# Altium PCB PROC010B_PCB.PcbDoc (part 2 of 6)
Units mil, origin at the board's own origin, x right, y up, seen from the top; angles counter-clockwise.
Board outline 3180 x 2565 mil, 6 copper layers (TOP, L2, L3, L4, L5, BOTTOM), stack 55.54 mil thick; 362 components, 264 nets, 1248 pads, 1144 vias.
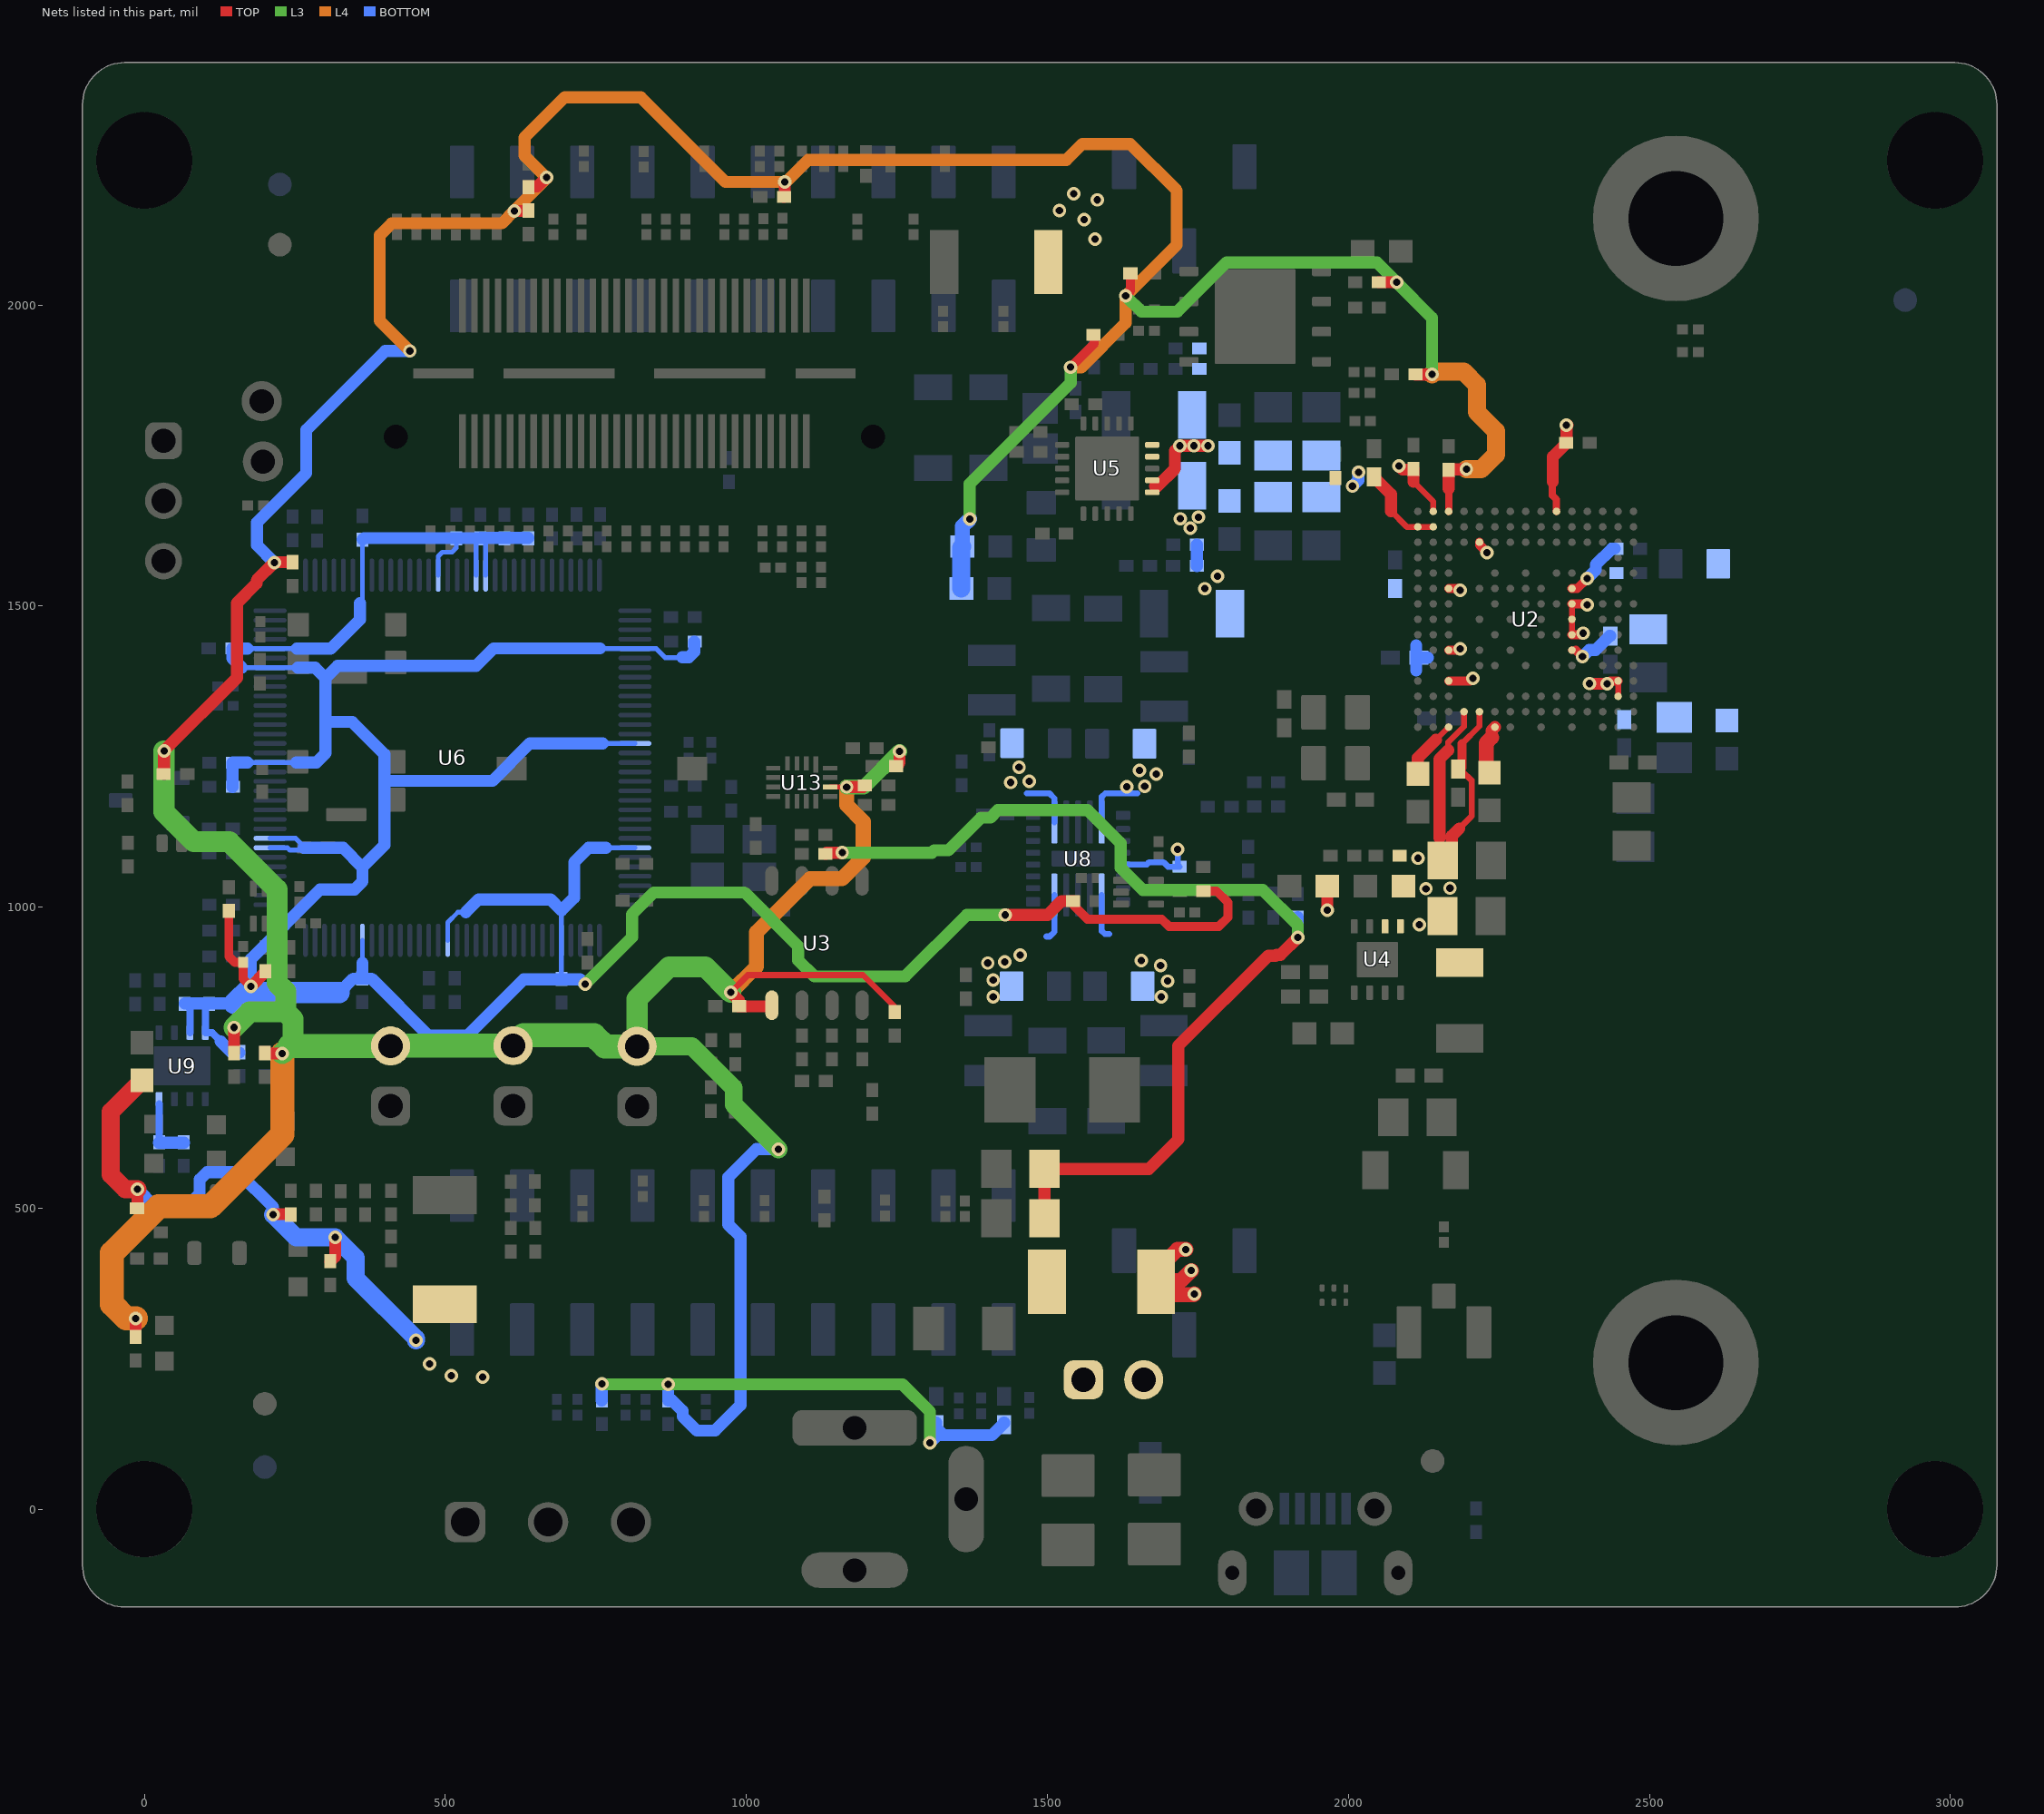
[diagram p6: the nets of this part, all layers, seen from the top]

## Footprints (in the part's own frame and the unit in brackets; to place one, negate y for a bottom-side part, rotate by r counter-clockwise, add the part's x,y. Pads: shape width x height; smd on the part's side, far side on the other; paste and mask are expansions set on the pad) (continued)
PDT0128A [mm] "Thin QFP, 128-Leads, Body 14x14mm, Pitch 0.4mm"
  oval 1.4x0.2 smd: 1(-7.7,6.2) 2(-7.7,5.8) 3(-7.7,5.4) 4(-7.7,5) 5(-7.7,4.6) 6(-7.7,4.2) 7(-7.7,3.8) 8(-7.7,3.4) 9(-7.7,3) 10(-7.7,2.6) 11(-7.7,2.2) 12(-7.7,1.8) 13(-7.7,1.4) 14(-7.7,1) 15(-7.7,0.6) 16(-7.7,0.2) 17(-7.7,-0.2) 18(-7.7,-0.6) 19(-7.7,-1) 20(-7.7,-1.4) 21(-7.7,-1.8) 22(-7.7,-2.2) 23(-7.7,-2.6) 24(-7.7,-3) 25(-7.7,-3.4) 26(-7.7,-3.8) 27(-7.7,-4.2) 28(-7.7,-4.6) 29(-7.7,-5) 30(-7.7,-5.4) 31(-7.7,-5.8) 32(-7.7,-6.2) 65(7.7,-6.2) 66(7.7,-5.8) 67(7.7,-5.4) 68(7.7,-5) 69(7.7,-4.6) 70(7.7,-4.2) 71(7.7,-3.8) 72(7.7,-3.4) 73(7.7,-3) 74(7.7,-2.6) 75(7.7,-2.2) 76(7.7,-1.8) 77(7.7,-1.4) 78(7.7,-1) 79(7.7,-0.6) 80(7.7,-0.2) 81(7.7,0.2) 82(7.7,0.6) 83(7.7,1) 84(7.7,1.4) 85(7.7,1.8) 86(7.7,2.2) 87(7.7,2.6) 88(7.7,3) 89(7.7,3.4) 90(7.7,3.8) 91(7.7,4.2) 92(7.7,4.6) 93(7.7,5) 94(7.7,5.4) 95(7.7,5.8) 96(7.7,6.2)
  oval 0.2x1.4 smd: 33(-6.2,-7.7) 34(-5.8,-7.7) 35(-5.4,-7.7) 36(-5,-7.7) 37(-4.6,-7.7) 38(-4.2,-7.7) 39(-3.8,-7.7) 40(-3.4,-7.7) 41(-3,-7.7) 42(-2.6,-7.7) 43(-2.2,-7.7) 44(-1.8,-7.7) 45(-1.4,-7.7) 46(-1,-7.7) 47(-0.6,-7.7) 48(-0.2,-7.7) 49(0.2,-7.7) 50(0.6,-7.7) 51(1,-7.7) 52(1.4,-7.7) 53(1.8,-7.7) 54(2.2,-7.7) 55(2.6,-7.7) 56(3,-7.7) 57(3.4,-7.7) 58(3.8,-7.7) 59(4.2,-7.7) 60(4.6,-7.7) 61(5,-7.7) 62(5.4,-7.7) 63(5.8,-7.7) 64(6.2,-7.7) 97(6.2,7.7) 98(5.8,7.7) 99(5.4,7.7) 100(5,7.7) 101(4.6,7.7) 102(4.2,7.7) 103(3.8,7.7) 104(3.4,7.7) 105(3,7.7) 106(2.6,7.7) 107(2.2,7.7) 108(1.8,7.7) 109(1.4,7.7) 110(1,7.7) 111(0.6,7.7) 112(0.2,7.7) 113(-0.2,7.7) 114(-0.6,7.7) 115(-1,7.7) 116(-1.4,7.7) 117(-1.8,7.7) 118(-2.2,7.7) 119(-2.6,7.7) 120(-3,7.7) 121(-3.4,7.7) 122(-3.8,7.7) 123(-4.2,7.7) 124(-4.6,7.7) 125(-5,7.7) 126(-5.4,7.7) 127(-5.8,7.7) 128(-6.2,7.7)
  silkscreen extent -7.7,-6.3 6.3,6.99, body extent -8,-8 8,8, height 1.07
RNF0026C [mm] "QFN, 26-Leads, Body 4x4.5mm, Pitch 0.5mm"
  rrect25% 0.6x0.4 smd paste-0.3: 1(-1.9,1.825) 8(-1.9,-1.825) 14(1.9,-1.825) 21(1.9,1.825)
  rrect40% 0.6x0.25 smd paste+0: 2(-1.9,1.25) 3(-1.9,0.75) 4(-1.9,0.25) 5(-1.9,-0.25) 6(-1.9,-0.75) 7(-1.9,-1.25) 15(1.9,-1.25) 16(1.9,-0.75) 17(1.9,-0.25) 18(1.9,0.25) 19(1.9,0.75) 20(1.9,1.25)
  rrect40% 0.25x1.82 smd paste-1: 9(-1,-1.54) 10(-0.5,-1.54) 11(0,-1.54) 12(0.5,-1.54) 13(1,-1.54) 22(1,1.54) 23(0.5,1.54) 24(0,1.54) 25(-0.5,1.54) 26(-1,1.54)
  rrect15% 2.24x0.66 smd paste-1: 27(0,0)
  rrect33% 0.6x0.3 on Bottom Paste: ""(-1.9,-1.775) ""(-1.9,1.775) ""(1.9,-1.775) ""(1.9,1.775)
  rrect33% 0.3x0.825 on Bottom Paste: ""(-1.575,-2.037) ""(-1.575,2.037) ""(1.575,-2.037) ""(1.575,2.037)
  rrect40% 0.25x0.81 on Bottom Paste: ""(-1,-2.045) ""(-1,-1.035) ""(-1,1.035) ""(-1,2.045) ""(-0.5,-2.045) ""(-0.5,-1.035) ""(-0.5,1.035) ""(-0.5,2.045) ""(0,-2.045) ""(0,-1.035) ""(0,1.035) ""(0,2.045) ""(0.5,-2.045) ""(0.5,-1.035) ""(0.5,1.035) ""(0.5,2.045) ""(1,-2.045) ""(1,-1.035) ""(1,1.035) ""(1,2.045)
  rrect15% 0.98x0.66 on Bottom Paste: ""(-0.59,0) ""(0.59,0)
  TOP region: -1.775,1.675 -1.775,2.4 -1.771,2.419 -1.76,2.435 -1.744,2.446 -1.725,2.45 -1.725,2.45 -1.475,2.45 -1.456,2.446 -1.44,2.435 -1.429,2.419 -1.425,2.4 -1.425,2.4 -1.425,1.675 -1.429,1.656 -1.44,1.64 -1.456,1.629 -1.475,1.625 -1.475,1.625 -1.725,1.625 -1.744,1.629 -1.76,1.64 -1.771,1.656 -1.775,1.675
  TOP region: 1.425,1.675 1.425,2.4 1.429,2.419 1.44,2.435 1.456,2.446 1.475,2.45 1.475,2.45 1.725,2.45 1.744,2.446 1.76,2.435 1.771,2.419 1.775,2.4 1.775,2.4 1.775,1.675 1.771,1.656 1.76,1.64 1.744,1.629 1.725,1.625 1.725,1.625 1.475,1.625 1.456,1.629 1.44,1.64 1.429,1.656 1.425,1.675
  TOP region: 1.425,-2.4 1.425,-1.675 1.429,-1.656 1.44,-1.64 1.456,-1.629 1.475,-1.625 1.475,-1.625 1.725,-1.625 1.744,-1.629 1.76,-1.64 1.771,-1.656 1.775,-1.675 1.775,-1.675 1.775,-2.4 1.771,-2.419 1.76,-2.435 1.744,-2.446 1.725,-2.45 1.725,-2.45 1.475,-2.45 1.456,-2.446 1.44,-2.435 1.429,-2.419 1.425,-2.4
  TOP region: -1.775,-2.4 -1.775,-1.675 -1.771,-1.656 -1.76,-1.64 -1.744,-1.629 -1.725,-1.625 -1.725,-1.625 -1.475,-1.625 -1.456,-1.629 -1.44,-1.64 -1.429,-1.656 -1.425,-1.675 -1.425,-1.675 -1.425,-2.4 -1.429,-2.419 -1.44,-2.435 -1.456,-2.446 -1.475,-2.45 -1.475,-2.45 -1.725,-2.45 -1.744,-2.446 -1.76,-2.435 -1.771,-2.419 -1.775,-2.4
  silkscreen extent -2.45,-2.7 2.45,2.7, body extent -2,-2.25 2,2.25, height 0.9
RSV0016A [mm] "QFN, 16-Leads, Body 1.8x2.6mm, Pitch 0.4mm, TI Recommended"
  rect 0.7x0.2 smd: 1(-0.75,0.6)
  rect 0.6x0.2 smd: 2(-0.8,0.2) 3(-0.8,-0.2) 4(-0.8,-0.6) 9(0.8,-0.6) 10(0.8,-0.2) 11(0.8,0.2) 12(0.8,0.6)
  rect 0.2x0.6 smd: 5(-0.6,-1.2) 6(-0.2,-1.2) 7(0.2,-1.2) 8(0.6,-1.2) 13(0.6,1.2) 14(0.2,1.2) 15(-0.2,1.2) 16(-0.6,1.2)
  silkscreen extent -1.08,-1.33 1.08,1.45, body extent -0.92,-1.32 0.92,1.33, height 0.56
RTJ0020D [mm] "QFN, 20-Leads, Body 4x4mm, Pitch 0.5mm, Thermal Pad 2.7x2.7mm, TI Recommended"
  rrect42% 0.6x0.24 smd: 1(-1.9,1) 2(-1.9,0.5) 3(-1.9,0) 4(-1.9,-0.5) 5(-1.9,-1) 11(1.9,-1) 12(1.9,-0.5) 13(1.9,0) 14(1.9,0.5) 15(1.9,1)
  rrect42% 0.24x0.6 smd: 6(-1,-1.9) 7(-0.5,-1.9) 8(0,-1.9) 9(0.5,-1.9) 10(1,-1.9) 16(1,1.9) 17(0.5,1.9) 18(0,1.9) 19(-0.5,1.9) 20(-1,1.9)
  rrect8% 1.19x1.19 on Top Paste: 21(-0.695,-0.695) 21(-0.695,0.695) 21(0.695,-0.695) 21(0.695,0.695)
  rrect4% 2.7x2.7 smd paste-1.4: 21(0,0)
  silkscreen extent -2.22,-2.22 2.23,2.23, body extent -2.07,-2.07 2.08,2.08, height 0.8
Samtec_QSH-030-01-X-D-A [mm] "Receptacle, 0.5 mm, 30x2, TH"
  rect 2.27x0.279 smd: 1(-2.865,7.25) 2(2.865,7.25) 3(-2.865,6.75) 4(2.865,6.75) 5(-2.865,6.25) 6(2.865,6.25) 7(-2.865,5.75) 8(2.865,5.75) 9(-2.865,5.25) 10(2.865,5.25) 11(-2.865,4.75) 12(2.865,4.75) 13(-2.865,4.25) 14(2.865,4.25) 15(-2.865,3.75) 16(2.865,3.75) 17(-2.865,3.25) 18(2.865,3.25) 19(-2.865,2.75) 20(2.865,2.75) 21(-2.865,2.25) 22(2.865,2.25) 23(-2.865,1.75) 24(2.865,1.75) 25(-2.865,1.25) 26(2.865,1.25) 27(-2.865,0.75) 28(2.865,0.75) 29(-2.865,0.25) 30(2.865,0.25) 31(-2.865,-0.25) 32(2.865,-0.25) 33(-2.865,-0.75) 34(2.865,-0.75) 35(-2.865,-1.25) 36(2.865,-1.25) 37(-2.865,-1.75) 38(2.865,-1.75) 39(-2.865,-2.25) 40(2.865,-2.25) 41(-2.865,-2.75) 42(2.865,-2.75) 43(-2.865,-3.25) 44(2.865,-3.25) 45(-2.865,-3.75) 46(2.865,-3.75) 47(-2.865,-4.25) 48(2.865,-4.25) 49(-2.865,-4.75) 50(2.865,-4.75) 51(-2.865,-5.25) 52(2.865,-5.25) 53(-2.865,-5.75) 54(2.865,-5.75) 55(-2.865,-6.25) 56(2.865,-6.25) 57(-2.865,-6.75) 58(2.865,-6.75) 59(-2.865,-7.25) 60(2.865,-7.25)
  round 0 hole 1.02 unplated mask+0: MH1(2.67,10.065) MH2(2.67,-10.065)
  rect 0.43x2.54 smd: MP1(0,8.065) MP4(0,-8.065)
  rect 0.43x4.7 smd: MP2(0,3.175) MP3(0,-3.175)
  silkscreen extent -3.9,-10.66 3.62,10.66, body extent -3.75,-10.64 3.75,10.67, height 3.25
Samtec_SSM-103-x-SV [mm] "Receptacle, 2.54mm, 3x1, SMT"
  rrect10% 1.02x1.905 smd: 1(-2.54,-1.777) 2(0,1.777) 3(2.54,-1.777)
  silkscreen extent -3.81,-2.27 3.81,1.28, body extent -3.81,-2.29 3.81,2.29, height 7.51
Samtec_SSM-110-x-DV [mm] "Receptacle, 2.54mm, 10x2, SMT"
  rrect10% 1.02x2.22 smd: 1(-11.43,2.825) 2(-11.43,-2.825) 3(-8.89,2.825) 4(-8.89,-2.825) 5(-6.35,2.825) 6(-6.35,-2.825) 7(-3.81,2.825) 8(-3.81,-2.825) 9(-1.27,2.825) 10(-1.27,-2.825) 11(1.27,2.825) 12(1.27,-2.825) 13(3.81,2.825) 14(3.81,-2.825) 15(6.35,2.825) 16(6.35,-2.825) 17(8.89,2.825) 18(8.89,-2.825) 19(11.43,2.825) 20(11.43,-2.825)
  silkscreen extent -13.02,-2.54 12.7,2.54, body extent -12.7,-3.52 12.7,3.52, height 7.42
Samtec_TSW-101-17-T-S [mm] "Samtec,CONN HEADER 1POS .100\" SNGL TIN"
  round 1.7 hole 1.02: 1(0,0)
  silkscreen extent -1.27,-1.27 1.27,1.27, body extent -1.27,-1.27 1.27,1.27, height 18.29
Samtec_TSW-103-07-T-S [mm] "Header, 2.54 mm, 3x1, TH"
  rrect50% 1.55x1.55 hole 1.02: 1(-2.54,0)
  round 1.55 hole 1.02: 2(0,0) 3(2.54,0)
  body extent -3.81,-1.27 3.81,1.27, height 8.39
SMB [mil] "Molded Diode, 2-Leads, Body 5.4x3.6mm, IPC Medium Density, based on OnSemi component dimensions"
  rect 85x107.99 smd: 1(-87.01,0) 2(87.01,0)
  silkscreen extent -155,-82 125,82, body extent -106,-71 106,71, height 91
SML-E1_Yellow [mm] "SMD, 2-Leads, Body 1.6x0.8mm"
  rect 0.8x0.8 smd: 1(0.825,0) 2(-0.825,0)
  silkscreen extent -1.8,-0.8 1.3,0.8, body extent -0.85,-0.45 0.85,0.45, height 0.46
SML-LX0603SRW_SuperRed [mm] "Lumex Opto/Components Inc"
  rect 0.8x0.8 smd: 1(-0.75,0) 2(0.75,0)
  silkscreen extent 1.4,-0.53 1.78,0.53, body extent -0.92,-0.53 0.92,0.53, height 1.1
SOD-882 [mm] "Skyworks"
  rrect42% 0.475x0.75 smd: 1(-0.412,0) 2(0.412,0)
  silkscreen extent -1.1,-0.35 -0.87,0.35, body extent -0.5,-0.3 0.5,0.3, height 0.5
SOT-23 [mm] "SOT23, 3-Leads, Body 2.9x1.3mm, Pitch 0.95mm, Lead Span 2.5mm, IPC Medium Density"
  rrect50% 1x0.6 smd: 1(-1.2,0.95) 2(-1.2,-0.95) 3(1.2,0)
  silkscreen extent -1.62,-1.5 0.7,1.5, body extent -1.16,-1.45 1.21,1.45, height 1
SW_CHS-01TB [mm] "CHS Recommended footprint"
  rect 1x1.27 smd: 1(0,3.81) 2(0,-3.81)
  silkscreen extent -1.8,-4.05 1.3,4.05, body extent -1.25,-4 1.25,4, height 2.51
SW_KMR243GLFG [mm] "SMD, 5-Leads, Body 4.2x2.8mm"
  rrect11% 0.9x1 smd: 1(-2.05,0.8) 2(2.05,0.8) 3(-2.05,-0.8) 4(2.05,-0.8)
  rrect18% 1.7x0.55 smd: 5(0,1.425)
  silkscreen extent -3.1,0.7 -2.9,0.9, body extent -2.3,-1.4 2.3,1.4, height 1.92
TI_Stacked_Overlay_Small [mil]
  silkscreen extent -418,-98 418,98
TSW-102-07-G-S [mm] "Samtec 100mil, 1x2, 230 mil above insulator"
  rrect50% 1.65x1.65 hole 1.016: 1(-1.27,0)
  round 1.65 hole 1.016: 2(1.27,0)
  body extent -2.54,-1.27 2.54,1.27, height 8.38
WEEE_Minimum [mil] "WEEElie bin"
  silkscreen extent -95,-172 99,104
WSON-8L_6x5MM_EP [mm] "SMD, 8-Leads, Body 6x5mm, Pitch 1.27mm"
  rrect25% 0.8x0.4 smd: 1(-2.8,1.905) 2(-2.8,0.635) 3(-2.8,-0.635) 4(-2.8,-1.905) 5(2.8,-1.905) 6(2.8,-0.635) 7(2.8,0.635) 8(2.8,1.905)
  rrect3% 3.4x4 smd paste-3: 9(0,0)
  rrect7% 1.468x1.698 on Top Paste: ""(-0.834,-0.949) ""(-0.834,0.949) ""(0.834,-0.949) ""(0.834,0.949)
  silkscreen extent -3.2,-2.7 3.2,2.7, body extent -3.05,-2.55 3.05,2.55, height 0.8

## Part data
C1 C13 C14 C33 C36 C91: library part CMP-0007136-5, "CAP, CERM, 1 uF, 16 V, +/- 10%, X7R, AEC-Q200 Grade 1, 0603", Cap_Case=0603, Manufacturer=MuRata, Supplier Part Number 1=490-5241-6-ND, TempCo=X7R, Tolerance_%=10%, Value1=Unknown, Value2=16V, ValueDisplayed=1uF
C2 C21: library part CMP-0006325-2, "CAP, CERM, 0.1 uF, 50 V, +/- 10%, X7R, AEC-Q200 Grade 1, 0402", Cap_Case=0402, Manufacturer=TDK, Supplier Part Number 1=445-6899-1-ND, TempCo=X7R, Tolerance_%=10%, Value1="0.039064 ohm", Value2=50V, ValueDisplayed=0.1uF
C3 C5 C7 C10 C12 C39 C47 C48 C51 C53 C56 C57 C68: library part CMP-0078265-1, "CAP, CERM, 0.22 µF, 16 V,+/- 10%, X7R, AEC-Q200 Grade 1, 0402", Cap_Case=0402, Manufacturer=MuRata, Supplier Part Number 1=490-10671-1-ND, TempCo=X7R, Tolerance_%=10%, Value2=16V, ValueDisplayed=0.22µF
C4 C6 C11: library part CMP-0006351-2, "CAP, CERM, 0.1 uF, 16 V, +/- 10%, X7R, 0402", Cap_Case=0402, Manufacturer=MuRata, Supplier Part Number 1=490-4759-2-ND, TempCo=X7R, Tolerance_%=10%, Value1=Unknown, Value2=16V, ValueDisplayed=0.1uF
C8: library part CMP-0078219-1, "CAP, CERM, 0.1 µF, 10 V,+/- 10%, X7S, 0201", Cap_Case=0201, Manufacturer=TDK, Supplier Part Number 1=445-9051-1-ND, TempCo=X7S, Tolerance_%=10%, Value2=10V, ValueDisplayed=0.1µF
C9 C15: library part CMP-0006367-2, "CAP, CERM, 4.7 pF, 50 V, +/- 2%, C0G/NP0, 0402", Cap_Case=0402, Manufacturer=MuRata, Supplier Part Number 1=490-8102-1-ND, TempCo=C0G/NP0, Tolerance_%=2%, Value1=Unknown, Value2=50V, ValueDisplayed=4.7pF
C16 C20 C42 C43 C49 C64 C67 C71 C75 C76 C79 C84 C85 C90: library part CMP-0078241-1, "CAP, CERM, 0.1 µF, 10 V,+/- 10%, X7R, 0402", Cap_Case=0402, Manufacturer=Kemet, Supplier Part Number 1=399-3520-1-ND, TempCo=X7R, Tolerance_%=10%, Value2=10V, ValueDisplayed=0.1µF
C17 C19 C23 C32 C34 C35 C37 C38 C40 C45 C52 C58 C59 C60 C65 C72 C73 C83: library part CMP-0008017-2, "CAP, CERM, 10 uF, 10 V, +/- 10%, X7R, 0805", Cap_Case=0805, Manufacturer=MuRata, Supplier Part Number 1=490-10674-1-ND, TempCo=X7R, Tolerance_%=10%, Value1=Unknown, Value2=10V, ValueDisplayed=10uF
C18 C22: library part CMP-0007138-4, "CAP, CERM, 0.47 uF, 16 V, +/- 10%, X7R, AEC-Q200 Grade 1, 0603", Cap_Case=0603, Manufacturer=MuRata, Supplier Part Number 1=490-4775-1-ND, TempCo=X7R, Tolerance_%=10%, Value1=Unknown, Value2=16V, ValueDisplayed=0.47uF
C24: library part CMP-0078221-1, "CAP, CERM, 4700 pF, 50 V,+/- 10%, X7R, 0402", Cap_Case=0402, Manufacturer=TDK, Supplier Part Number 1=445-1258-1-ND, TempCo=X7R, Tolerance_%=10%, Value2=50V, ValueDisplayed=4700pF
C25 C30 C31: library part CMP-0008770-2, "CAP, CERM, 22 uF, 6.3 V, +/- 10%, X7R, AEC-Q200 Grade 1, 1206", Cap_Case=1206_180, Manufacturer=TDK, Supplier Part Number 1=445-7884-1-ND, TempCo=X7R, Tolerance_%=10%, Value1="0.001872 ohm", Value2=6.3V, ValueDisplayed=22uF
C26 C27: library part CMP-0078216-1, "CAP, TA, 47 µF, 10 V, +/- 10%, SMD", Cap_Case=3528-21, Manufacturer=Kemet, Supplier Part Number 1=399-9728-1-ND, Tolerance_%=10%, Value2=10V, ValueDisplayed=47µF
C28 C29 C44 C46: library part CMP-0078224-1, "CAP, CERM, 0.01 µF, 50 V,+/- 10%, X8R, AEC-Q200 Grade 0, 0402", Cap_Case=0402, Manufacturer=TDK, Supplier Part Number 1=445-12303-1-ND, TempCo=X8R, Tolerance_%=10%, Value2=50V, ValueDisplayed=0.01µF
C41 C61 C62: library part CMP-0078222-1, "CAP, CERM, 1 µF, 6.3 V,+/- 20%, X7S, 0402", Cap_Case=0402, Manufacturer=TDK, Supplier Part Number 1=445-9080-1-ND, TempCo=X7S, Tolerance_%=20%, Value2=6.3V, ValueDisplayed=1µF
C50: library part CMP-0078220-1, "CAP, CERM, 0.01 µF, 25 V,+/- 10%, X7R, 0402", Cap_Case=0402, Manufacturer=TDK, Supplier Part Number 1=445-1260-1-ND, TempCo=X7R, Tolerance_%=10%, Value2=25V, ValueDisplayed=0.01µF
C54 C55 C81 C82: library part CMP-0008811-2, "CAP, CERM, 22 uF, 10 V, +/- 10%, X7R, AEC-Q200 Grade 1, 1206", Cap_Case=1206, Manufacturer=MuRata, TempCo=X7R, Tolerance_%=10%, Value1=Unknown, Value2=10V, ValueDisplayed=22uF
C63 C70: library part CMP-0006494-2, "CAP, CERM, 8 pF, 50 V, +/- 6%, C0G/NP0, 0402", Cap_Case=0402, Manufacturer=MuRata, Supplier Part Number 1=490-5867-1-ND, TempCo=C0G/NP0, Tolerance_%=6%, Value1=Unknown, Value2=50V, ValueDisplayed=8pF
C66 C69: library part CMP-0078218-1, "CAP, CERM, 0.01 µF, 16 V,+/- 10%, X7R, 0402", Cap_Case=0402, Manufacturer=Kemet, Supplier Part Number 1=399-1038-1-ND, TempCo=X7R, Tolerance_%=10%, Value2=16V, ValueDisplayed=0.01µF
C74 C77 C80: library part CMP-0006302-2, "CAP, CERM, 2.2 uF, 10 V, +/- 10%, X7S, 0402", Cap_Case=0402_065, Manufacturer=TDK, Supplier Part Number 1=445-9097-1-ND, TempCo=X7S, Tolerance_%=10%, Value1="0.005925 ohm", Value2=10V, ValueDisplayed=2.2uF
C78: library part CMP-0078217-1, "CAP, CERM, 15 pF, 50 V,+/- 1%, C0G/NP0, 0402", Cap_Case=0402, Manufacturer=AVX, Supplier Part Number 1=478-5126-1-ND, TempCo=C0G/NP0, Tolerance_%=1%, Value2=50V, ValueDisplayed=15pF
C86 C87 C88 C89: library part CMP-0078223-1, "CAP, CERM, 390 pF, 50 V,+/- 5%, C0G/NP0, AEC-Q200 Grade 0, 0402", Cap_Case=0402, Manufacturer=TDK, Supplier Part Number 1=445-12137-1-ND, TempCo=C0G/NP0, Tolerance_%=5%, Value2=50V, ValueDisplayed=390pF
"CAUTION HOT SURFACE1": library part CMP-0074837-1, "IEC 61010-1 Hot Surface Warning"
D2: library part CMP-0078187-1, "Diode, Schottky,  V, 0.01 A, SOD-882", Manufacturer="Skyworks Solutions", Value1=0.01A, Value2=0.34V
D3: library part CMP-0078243-1, "Diode, TVS, Uni, 5.8 V, 10.5 Vc, AEC-Q101, SMB", Manufacturer=Littelfuse, Power_W=550mW, Supplier Part Number 1=SZP6SMB6.8AT3G-ND, Value1=0.55W
DS1 DS2 DS5: library part CMP-0002876-1, "LED, Super Red, SMD", Color="super red", Manufacturer=Lumex, Supplier Part Number 1=67-1551-1-ND, Value1=W, Value2=1.7V
DS3 DS4: library part CMP-0002977-2, "LED, Yellow, SMD", Color=yellow, Manufacturer=Rohm, Power_TotalModule=54mW, Supplier Part Number 1=511-1588-1-ND, Value1=0.054W, Value2=2.2V
"ESD Susceptible1": library part CMP-0074840-1, "ESD Susceptible Symbol"
F1: library part CMP-0003458-2, "Fuse, 5 A, 32VAC/VDC, SMD", Irating_A=5A, Manufacturer=Littelfuse, Supplier Part Number 1=F1608CT-ND
FB1 FB2: library part CMP-0003364-1, "Ferrite Bead, 30 ohm @ 100 MHz, 4 A, 0805", Manufacturer=MuRata, Supplier Part Number 1=490-11049-1-ND, Value1="0.014 ohm", Value2=4A, ValueDisplayed="30 ohm"
FID1 FID2 FID3 FID4 FID5 FID6 FID7: library part CMP-0077181-1, "Fiducial mark.  There is nothing to buy or mount.", Manufacturer=N/A
J1: library part CMP-0075524-1, "Receptacle, 0.5 mm, 30x2, Gold, TH", Color=Black, Manufacturer=Samtec, Supplier Part Number 1=SAM8180-ND
J2: library part CMP-0055788-1, "UMC Straight Jack Receptacle, 50 Ohm, Gold, SMT", Manufacturer="Cinch Connectivity", Supplier Part Number 1=J983CT-ND
J3: library part CMP-0075352-1, "Terminal Block, 3.5mm, 3x1, Tin, R/A, TH", Color=Blue, Current_A=10A, Manufacturer="On-Shore Technology", Supplier Part Number 1=ED2636-ND, Voltage_V=125V
J4 J7: library part CMP-0078183-1, "Receptacle, 2.54mm, 3x1, Gold with Tin tail, SMT", Color=Black, Current_A=5.2A, Manufacturer=Samtec, Supplier Part Number 1=SAM1152-03-ND, Voltage_V=405V
J5 J6: library part CMP-0078182-1, "Receptacle, 2.54mm, 10x2, Gold with Tin tail, SMT", Color=Black, Current_A=5.2A, Manufacturer=Samtec, Supplier Part Number 1=SAM1150-10-ND, Voltage_V=405V
J8: library part CMP-0055293-1, "Connector, Receptacle, Micro-USB Type B, R/A, Bottom Mount SMT", Manufacturer=Molex, Supplier Part Number 1=WM1399CT-ND
L1 L2 L3 L4: library part CMP-0058946-1, "Inductor, Shielded, 470 nH, 4.7 A, 0.021 ohm, SMD", Manufacturer="MuRata Toko", PartNumber=DFE252012P-R47M{}P2, Value1="0.021 ohm", Value2=4.7A, ValueDisplayed=470nH
L5 L7 L8 L9: library part CMP-0083745-1, "Inductor, Wirewound, Ferrite, 100 nH, 2.85 A, 0.024 ohm, AEC-Q200 Grade 1, SMD", Manufacturer=TDK, Value1="0.024 ohm", Value2=2.85A, ValueDisplayed=100nH
LBL1: library part CMP-0003625-1, "Thermal Transfer Printable Labels, 0.650\" W x 0.200\" H - 10,000 per roll", Manufacturer=Brady, PartNumber=THT-14-423-10, Supplier Part Number 1=97C5133
Logo1: library part CMP-0074838-1, "Texas Instrument Corporate Signature"
Logo2: library part CMP-0074847-1, "FCC_disclaimer"
Logo3: library part CMP-0074769-1
LOGO4: library part CMP-0074844-1
P1: library part CMP-0075530-2, "Header, 2.54 mm, 3x1, Tin, TH", Color=Black, Current_A=6.3A, Manufacturer=Samtec, Supplier Part Number 1=SAM1035-03-ND, Voltage_V=550V
P2 P3 P4 P5: library part CMP-0075405-2, "Header, 100mil, 2x1, Gold, TH", Color=Black, Current_A=6.3A, Manufacturer=Samtec, Supplier Part Number 1=SAM1029-02-ND, Voltage_V=550V
P6: library part CMP-0078270-1, "DC POWER JACK, R/A, TH", Color=Black, Current_A=5A, Manufacturer="CUI Inc.", Supplier Part Number 1=CP-002AH-ND, Voltage_V=4.5-5.5V
Q1 Q2: library part CMP-0000947-2, "MOSFET, N-CH, 100 V, 0.17 A, SOT-23", Alternate Manufacturer=None, Manufacturer="Fairchild Semiconductor", Supplier Part Number 1=BSS123NCT-ND, Value1=1, Value2="1.8 nC"
R1 R2 R3 R4 R5 R6 R7 R8 R9 R10 R17 R18 R19 R20 R21 R22 R23 R24 R25 R26 R27 R28 R29 R30 R31 R32 R33 R35 R36 R48 R49 R50 R51 R52 R53 R54 R55 R56 R57 R58 R59 R60 R61 R62 R63 R64 R65 R66 R67 R69 R70 R71 R72 R75 R76 R94 R102 R104 R105 R106 R108 R109 R111 R135 R136 R144 R146 R162 R163 R164 R165 R166 R167 R168 R169 R180 R181 R182 R185 R186 R188 R197 R198: library part CMP-0027008-4, "RES, 0, 5%, 0.05 W, 0201", Manufacturer=Vishay-Dale, Power_W=50mW, Supplier Part Number 1=72M6743, TempCo=ppm/C, Tolerance_%=5%, Value2=0.05W, Value_Code=0000, ValueDisplayed=0
R11 R12 R37 R78 R97 R107 R119 R120 R128 R129 R141 R152 R159 R177 R183 R187: library part CMP-0026992-2, "RES, 0, 5%, 0.063 W, 0402", Manufacturer=Panasonic, Power_W=63mW, Supplier Part Number 1=P0.0JCT-ND, TempCo="600 ppm/C", Tolerance_%=5%, Value2=0.063W, Value_Code=0000, ValueDisplayed=0
R13 R14 R15 R16 R41 R43 R46 R47 R73 R74 R81 R83 R84 R86 R89 R91 R98 R113 R145 R148 R155 R178 R179 R184 R196: library part CMP-0025958-3, "RES, 10.0 k, 1%, 0.063 W, AEC-Q200 Grade 0, 0402", Manufacturer=Vishay-Dale, Power_W=63mW, Supplier Part Number 1=541-10.0KLCT-ND, TempCo="100 ppm/C", Tolerance_%=1%, Value2=0.063W, Value_Code=10k0, ValueDisplayed=10.0k
R34 R115 R118: library part CMP-0016044-3, "RES, 0, 5%, 0.75 W, AEC-Q200 Grade 0, 2010", Manufacturer=Vishay-Dale, Power_W=750mW, Supplier Part Number 1=541-0.0WCT-ND, TempCo=ppm/C, Tolerance_%=5%, Value2=0.75W, Value_Code=0000, ValueDisplayed=0
R38: library part CMP-0026395-2, "RES, 47.5 k, 1%, 0.063 W, AEC-Q200 Grade 0, 0402", Manufacturer=Vishay-Dale, Power_W=63mW, Supplier Part Number 1=541-47.5KLCT-ND, TempCo="100 ppm/C", Tolerance_%=1%, Value2=0.063W, Value_Code=47k5, ValueDisplayed=47.5k
R39 R40 R42 R44 R45: library part CMP-0027275-3, "RES, 33.2, 1%, 0.05 W, 0201", Manufacturer=Vishay-Dale, Power_W=50mW, Supplier Part Number 1=541-33.2ABCT-ND, TempCo="200 ppm/C", Tolerance_%=1%, Value2=0.05W, Value_Code=33R2, ValueDisplayed=33.2
R68 R77 R79 R80 R154: library part CMP-0026993-2, "RES, 100, 5%, 0.1 W, AEC-Q200 Grade 0, 0402", Manufacturer=Panasonic, Power_W=100mW, Supplier Part Number 1=P100JCT-ND, TempCo="200 ppm/C", Tolerance_%=5%, Value2=0.1W, Value_Code=100R, ValueDisplayed=100
R82: library part CMP-0025993-3, "RES, 12.7 k, 1%, 0.063 W, AEC-Q200 Grade 0, 0402", Manufacturer=Vishay-Dale, Power_W=63mW, Supplier Part Number 1=541-12.7KLCT-ND, TempCo="100 ppm/C", Tolerance_%=1%, Value2=0.063W, Value_Code=12k7, ValueDisplayed=12.7k
R85 R87: library part CMP-0026491-2, "RES, 61.9, 1%, 0.063 W, AEC-Q200 Grade 0, 0402", Manufacturer=Vishay-Dale, Power_W=63mW, Supplier Part Number 1=541-61.9LCT-ND, TempCo="100 ppm/C", Tolerance_%=1%, Value2=0.063W, Value_Code=61R9, ValueDisplayed=61.9
R88 R96 R114: library part CMP-0026574-2, "RES, 82.5 k, 1%, 0.063 W, AEC-Q200 Grade 0, 0402", Manufacturer=Vishay-Dale, Power_W=63mW, Supplier Part Number 1=541-82.5KLCT-ND, TempCo="100 ppm/C", Tolerance_%=1%, Value2=0.063W, Value_Code=82k5, ValueDisplayed=82.5k
R90 R189: library part CMP-0078194-1, "RES, 360, 5%, 0.1 W, AEC-Q200 Grade 0, 0402", Manufacturer=Panasonic, Power_W=100mW, Supplier Part Number 1=P360JCT-ND, TempCo="200 ppm/C", Tolerance_%=5%, Value2=0.1W, Value_Code=360R, ValueDisplayed=360
R92 R95 R99: library part CMP-0026557-2, "RES, 7.87 k, 1%, 0.063 W, AEC-Q200 Grade 0, 0402", Manufacturer=Vishay-Dale, Power_W=63mW, Supplier Part Number 1=541-7.87KLCT-ND, TempCo="100 ppm/C", Tolerance_%=1%, Value2=0.063W, Value_Code=7k87, ValueDisplayed=7.87k
R93 R101 R112: library part CMP-0026542-2, "RES, 750, 1%, 0.063 W, AEC-Q200 Grade 0, 0402", Manufacturer=Vishay-Dale, Power_W=63mW, Supplier Part Number 1=541-750LCT-ND, TempCo="100 ppm/C", Tolerance_%=1%, Value2=0.063W, Value_Code=750R, ValueDisplayed=750
R100 R103 R116 R117 R160: library part CMP-0078212-1, "RES, 510, 5%, 0.1 W, AEC-Q200 Grade 0, 0402", Manufacturer=Panasonic, Power_W=100mW, Supplier Part Number 1=P510JCT-ND, TempCo="200 ppm/C", Tolerance_%=5%, Value2=0.1W, Value_Code=510R, ValueDisplayed=510
R110 R138 R158 R172 R173: library part CMP-0025950-3, "RES, 100 k, 1%, 0.063 W, AEC-Q200 Grade 0, 0402", Manufacturer=Vishay-Dale, Power_W=63mW, Supplier Part Number 1=541-100KLCT-ND, TempCo="100 ppm/C", Tolerance_%=1%, Value2=0.063W, Value_Code=100k
R121 R132: library part CMP-0078211-2, "RES, 3.00 k, 1%, 0.063 W, AEC-Q200 Grade 0, 0402", Manufacturer=Vishay-Dale, Power_W=63mW, Supplier Part Number 1=52K6934, TempCo="100 ppm/C", Tolerance_%=1%, Value2=0.063W, Value_Code=3k00, ValueDisplayed=3.00k
R122 R131 R139: library part CMP-0026099-2, "RES, 1.96 k, 1%, 0.063 W, AEC-Q200 Grade 0, 0402", Manufacturer=Vishay-Dale, Power_W=63mW, Supplier Part Number 1=541-1.96KLCT-ND, TempCo="100 ppm/C", Tolerance_%=1%, Value2=0.063W, Value_Code=1k96, ValueDisplayed=1.96k
R123 R124 R126 R127 R140: library part CMP-0026071-3, "RES, 1.00 k, 1%, 0.063 W, AEC-Q200 Grade 0, 0402", Manufacturer=Vishay-Dale, Power_W=63mW, Supplier Part Number 1=541-1.00KLCT-ND, TempCo="100 ppm/C", Tolerance_%=1%, Value2=0.063W, Value_Code=1k00, ValueDisplayed=1.00k
R125 R195: library part CMP-0025958-2, "RES, 10.0 k, 1%, 0.063 W, 0402", Manufacturer=Vishay-Dale, Power_W=63mW, Supplier Part Number 1=541-10.0KLCT-ND, TempCo="100 ppm/C", Tolerance_%=1%, Value2=0.063W, Value_Code=10k0, ValueDisplayed=10.0k
R130 R133 R137 R161 R175 R176: library part CMP-0025884-3, "RES, 0, 5%, 0.125 W, 0603", Manufacturer=Vishay/Beyschlag, Power_W=125mW, Supplier Part Number 1=MCT0603-0.0-ZZCT-ND, TempCo=ppm/C, Tolerance_%=5%, Value2=0.125W, Value_Code=0000, ValueDisplayed=0
R134: library part CMP-0026404-2, "RES, 49.9, 1%, 0.063 W, AEC-Q200 Grade 0, 0402", Manufacturer=Vishay-Dale, Power_W=63mW, Supplier Part Number 1=541-49.9LCT-ND, TempCo="100 ppm/C", Tolerance_%=1%, Value2=0.063W, Value_Code=49R9, ValueDisplayed=49.9
R142 R150: library part CMP-0026701-1, "RES, 4.99 k, 1%, 0.1 W, AEC-Q200 Grade 0, 0402", Manufacturer=Panasonic, Power_W=100mW, Supplier Part Number 1=P4.99KLCT-ND, TempCo="100 ppm/C", Tolerance_%=1%, Value2=0.1W, Value_Code=4k99, ValueDisplayed=4.99k
R143 R147: library part CMP-0026414-2, "RES, 4.99 k, 1%, 0.063 W, AEC-Q200 Grade 0, 0402", Manufacturer=Vishay-Dale, Power_W=63mW, Supplier Part Number 1=541-4.99KLCT-ND, TempCo="100 ppm/C", Tolerance_%=1%, Value2=0.063W, Value_Code=4k99, ValueDisplayed=4.99k
R149: library part CMP-0078193-1, "RES, 1.0 k, 5%, 0.1 W, AEC-Q200 Grade 0, 0402", Manufacturer=Panasonic, Power_W=100mW, Supplier Part Number 1=P1.0KJCT-ND, TempCo="200 ppm/C", Tolerance_%=5%, Value2=0.1W, Value_Code=1k00, ValueDisplayed=1.0k
R151 R153: library part CMP-0078210-2, "RES, 330 k, 1%, 0.063 W, AEC-Q200 Grade 0, 0402", Manufacturer=Vishay-Dale, Power_W=63mW, Supplier Part Number 1=541-330KLCT-ND, TempCo="100 ppm/C", Tolerance_%=1%, Value2=0.063W, Value_Code=330k
R156: library part CMP-0026403-2, "RES, 49.9 k, 1%, 0.063 W, AEC-Q200 Grade 0, 0402", Manufacturer=Vishay-Dale, Power_W=63mW, Supplier Part Number 1=541-49.9KLCT-ND, TempCo="100 ppm/C", Tolerance_%=1%, Value2=0.063W, Value_Code=49k9, ValueDisplayed=49.9k
R157 R174: library part CMP-0078244-2, "RES, 30.0 k, 1%, 0.063 W, AEC-Q200 Grade 0, 0402", Manufacturer=Vishay-Dale, Power_W=63mW, Supplier Part Number 1=541-30.0KLCT-ND, TempCo="100 ppm/C", Tolerance_%=1%, Value2=0.063W, Value_Code=30k0, ValueDisplayed=30.0k
R170 R171: library part CMP-0026244-2, "RES, 2.94 k, 1%, 0.063 W, AEC-Q200 Grade 0, 0402", Manufacturer=Vishay-Dale, Power_W=63mW, Supplier Part Number 1=541-2.94KLCT-ND, TempCo="100 ppm/C", Tolerance_%=1%, Value2=0.063W, Value_Code=2k94, ValueDisplayed=2.94k
R190 R191 R192 R193: library part CMP-0026363-2, "RES, 3.83, 1%, 0.063 W, AEC-Q200 Grade 0, 0402", Manufacturer=Vishay-Dale, Power_W=63mW, Supplier Part Number 1=541-3.83LLCT-ND, TempCo="100 ppm/C", Tolerance_%=1%, Value2=0.063W, Value_Code=3R83, ValueDisplayed=3.83
R194: library part CMP-0026413-2, "RES, 4.87 k, 1%, 0.063 W, AEC-Q200 Grade 0, 0402", Manufacturer=Vishay-Dale, Power_W=63mW, Supplier Part Number 1=541-4.87KLCT-ND, TempCo="100 ppm/C", Tolerance_%=1%, Value2=0.063W, Value_Code=4k87, ValueDisplayed=4.87k
S1: library part CMP-0002163-2, "Switch, Slide, SPST, Top Slide, SMT", CurrentRating_mA=100A, Manufacturer="Copal Electronics", Supplier Part Number 1=563-1004-1-ND
SW1 SW2: library part CMP-0002325-1, "Switch, SPST-NO, Off-Mom, 0.01 A, 32 VDC, SMD", CurrentRating_mA=10A, Manufacturer="C&K Components", Supplier Part Number 1=401-1432-2-ND
TP1 TP2: library part CMP-0055993-1, "Header, 100mil, 1x1, Tin, TH", Color=Black, Current_A=6.3A, Manufacturer=Samtec, Supplier Part Number 1=SAM1067-01-ND, Voltage_V=550V
U1: library part CMP-0079267-1, "2.3V-3.6V, 16M-BIT [x 1/x 2/x 4] CMOS FLASH Memory, WSON-8", Manufacturer="Macronix International Co., LTD", Supplier Part Number 1=1092-1211-ND
U2: library part CMP-0081285-1, "Single Chip 77 and 79 GHz FMCW Transceiver, ABL0161A (FCBGA-161)", Alternate Manufacturer="Texas Instruments", Alternate PartNumber=AWR1243FBIGABLRQ1
U3: library part CMP-0075992-1, "Automotive Fault Protected CAN Transceiver With Flexible Data-Rate, D0008A (SOIC-8)", Alternate Manufacturer="Texas Instruments", Alternate PartNumber=TCAN1042HGVDRQ1
U4: library part CMP-0073870-2, "Automotive Low-Noise, Wide-Bandwidth, High PSRR, Low-Dropout 1-A Linear Regulator, DRB0008A (VSON-8)", Alternate Manufacturer="Texas Instruments"
U5: library part CMP-0073732-2, "Dual, 1-A, Low Noise (3.8-uVRMS), LDO Voltage Regulator, RTJ0020D (WQFN-20)", Alternate Manufacturer="Texas Instruments", Alternate PartNumber=TPS7A8801RTJT
U6: library part CMP-0029856-2, "Tiva C Series Microcontroller, 1024 KB Flash, 256 KB SRAM, 12 Bit, 20 Channels, -40 to 105 degC, 128-Pin TQFP (PDT), Green (RoHS & no Sb/Br), Tray", Manufacturer="Texas Instruments", Temperature Range="-40 to 105 degC"
U7: library part CMP-0033001-1, "Precision Micropower Shunt Voltage Reference, 0.5% accuracy, 2.5 V, 15 ppm / degC, 15 mA, -40 to 125 degC, 3-pin SOT-23 (DBZ), Green (RoHS & no Sb/Br)", Manufacturer="Texas Instruments", Rating=Catalog, Temp Coeff(Max)(ppm/ degree C)=100, Temp Coeff(Typ)(ppm/ degree C)=15
U8: library part CMP-0079120-1, "4-A + 2.5-A + Two 1.5-A Buck Converters With Integrated Switches, RNF0026C (VQFN-HR-26)", Alternate Manufacturer="Texas Instruments", Alternate PartNumber=LP87524JRNFTQ1
U9: library part CMP-0036402-3, "Single Output High PSRR LDO, 1 A, Adjustable 1.2 to 5.5 V Output, 2.7 to 5.5 V Input, 8-pin SON (DRB), -40 to 125 degC, Green (RoHS & no Sb/Br)", Manufacturer="Texas Instruments"
U10: library part CMP-0043115-2, "ESD-Protection Array for High-Speed Data Interfaces, 4 Channels, -40 to +85 degC, 6-pin SON (DRY), Green (RoHS & no Sb/Br)", Breakdown Voltage(Min)(V)=6, IO Capacitance(Typ)(pF)=1.6, IO Leakage Current(nA)=1, Manufacturer="Texas Instruments"
U11 U12: library part CMP-0067397-2, "1.4V-Capable +/-0.5degC Temperature Sensor with Alert Function and I2C/SMBus interface in SOT-563, DRL0006A (SOT-OTHER-6)", Alternate Manufacturer="Texas Instruments", Alternate PartNumber=TMP112AIDRLT
U13: library part CMP-0067415-1, "10-Ohm Quad SPDT Analog Switch, RSV0016A (UQFN-16)", Alternate Manufacturer="Texas Instruments"
Y1: library part CMP-0004694-3, "Crystal, 40 MHz, 8pF, SMD", Frequency_Fixed=40MHz, Frequency Stability=+/-200ppm, Manufacturer=Kyocera, Supplier Part Number 1=581-CX3225SA40D0PTWC
Y2: library part CMP-0078214-2, "Crystal, 16 MHz, 15 ppm, 8 pF, AEC-Q200 Grade 1, SMD", Frequency_Fixed=16MHz, Frequency Stability="150 ppm", Frequency Tolerance="10 ppm", Load Capacitance="7.36 pF", Manufacturer=NDK, Supplier Part Number 1=644-1129-1-ND
ZZ1: library part CMP-0003616-3
ZZ2: library part CMP-0077236-1
ZZ3: library part CMP-0077237-1
ZZ4: library part CMP-0077238-1
ZZ5: library part CMP-0077238-1, "Micro USB cable, Brackets, Screws, Nuts, Jumpers and Bump on need to be placed in a platic bag"

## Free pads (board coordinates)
  round 275.59 hole 157.48: 0(2543.95,2143.55) 1(2543.95,243.55)
  round 160 hole 160 unplated: ""(0,0) ""(0,2240) ""(2974.5,0) ""(2974.5,2240)

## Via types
v1: diameter 22.4, hole 12.2, TOP to BOTTOM, tented both sides, 621 vias
v2: diameter 13.77/15.74 (per signal layer), hole 5.9, TOP to L2, tented top, 508 vias
v3: diameter 19.68, hole 7.87, TOP to BOTTOM, tented top, 7 vias
v4: diameter 19.68, hole 7.87, TOP to BOTTOM, 4 vias
v5: diameter 19.68, hole 7.87, TOP to BOTTOM, tented both sides, 3 vias
v6: diameter 19.68, hole 7.87, TOP to BOTTOM, tented bottom, 1 vias

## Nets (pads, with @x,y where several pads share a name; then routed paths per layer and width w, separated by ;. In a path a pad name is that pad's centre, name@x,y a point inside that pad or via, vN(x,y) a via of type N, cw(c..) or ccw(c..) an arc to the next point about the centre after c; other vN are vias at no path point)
3V3_BRD: C41.2 C42.2 C43.2 C50.2 C61.2 C76.2 C77.2 C78.2 R124.2 R127.2 R134.2 R140.2 R155.2 R156.2 R179.2 R183.2 R184.2 R187.2 R188.1 U6.7 U6.8 U6.16 U6.26 U6.28 U6.39 U6.47 U6.51 U6.52 U6.69 U6.79 U6.90 U6.101 U6.113 U6.122 U9.3 U9.4 | length 6461.6
  TOP w15: R184.2@140.38,994.45 R184.2@140.38,993.66 140.38,918.01 150.16,908.23 R188.1@163.83,908.23 163.83,881.17 v1(177,868) ; R179.2@1543.45,1009.92 1543.45,1003.19 1566.64,980 1690,980 1702,968 1784.72,968 1799.73,983.01 1799.73,1007.95 1781,1026.68 R183.2@1759.34,1026.68 R183.2@1758.55,1026.68
  TOP w20: v1(177,868) 200.98,891.98 R187.2@200.98,893.66 ; v1(1430,987) 1500.36,987 1523.28,1009.92 R179.2@1542.66,1009.92 R179.2@1543.45,1009.92
  L3 w20: v1(732,872) 810.21,950.21 810.21,988.21 846.3,1024.3 996.79,1024.3 1086.18,934.9 1086.18,911.5 1112.78,884.9 1263.9,884.9 1366,987 v1(1430,987)
  BOTTOM w8: 161.85,1397.65 254.85,1397.65 ; 171.33,1240.17 252.33,1240.17 ; 171.36,1429.14 253.36,1429.14 ; U6.7@208.64,1098.43 238.07,1098.43 242,1094.5 260.32,1094.5 264.25,1098.43 264.25,1101.25 251.32,1114.18 U6.8@208.64,1114.18 ; 362.18,907.32 U6.122@362.18,944.89 ; 362.18,1508.68 C43.2@362.18,1610.21 ; U6.47@488.17,1551.19 488.17,1582.5 495.15,1589.48 511.07,1589.48 518.22,1596.62 C42.2@518.22,1612.16 ; U6.113@503.92,944.89 503.92,974.56 520.86,991.5 534,991.5 ; C42.2@518.03,1612.36 C42.2@518.22,1612.55 ; U6.51@551.16,1551.19 551.16,1605.41 558.3,1612.55 566.91,1603.94 U6.52@566.91,1551.19 ; R155.2@692.89,880.16 692.89,994.61 ; 757,1429.5 757.36,1429.14 850.37,1429.14 865.11,1414.4 892.75,1414.4 ; 761.16,1271.66 U6.79@814.94,1271.66 ; 767,1098.5 814.87,1098.5 U6.90@814.94,1098.43
  BOTTOM w8.4: 358,1504.5 362.18,1508.68 ; C43.2@362.18,1610.21 C43.2@362.52,1610.55 ; R155.2@692.78,880.05 R155.2@692.89,880.16 ; 892.75,1414.4 893.34,1414.99
  BOTTOM w12: C78.2@67.1,839.85 75.63,831.32 U9.3@75.63,791.44 ; C77.2@108.82,839.85 101.22,832.25 U9.4@101.22,791.44 112.56,791.44 127,777
  BOTTOM w20: C78.2@67.1,839.85 108.82,839.85 148.85,839.85 ; 127,777 145.91,758.09 R156.2@158.03,758.09 ; R140.2@146.55,1199.52 146.55,1239.66 147.06,1240.17 171.33,1240.17 ; 161.85,1397.65 145.95,1413.55 145.95,1429.4 146.21,1429.14 171.36,1429.14 ; v1(177,868) 177,914 292,1029 349,1029 362.18,1042.18 362.18,1066.32 ; 252.33,1240.17 285.67,1240.17 301,1255.5 301,1307.5 ; 253.36,1429.14 309.64,1429.14 358,1477.5 358,1504.5 ; 254.85,1397.65 283.85,1397.65 301,1380.5 ; 264.25,1098.43 330.07,1098.43 362.18,1066.32 ; 324.01,858 347.16,881.15 C76.2@361.92,881.15 ; 362.18,907.32 362.18,881.41 C76.2@361.92,881.15 ; C43.2@362.52,1610.55 364.52,1612.55 518.22,1612.55 558.3,1612.55 558.7,1612.95 R124.2@637.72,1612.95 ; 534,991.5 555,1012.5 675,1012.5 692.89,994.61 714,1015.72 714,1074.5 738,1098.5 767,1098.5 ; v1(732,872) 723.95,880.05 692.78,880.05 630.21,880.05 536.46,786.3 472.2,786.3 377.35,881.15 C76.2@361.92,881.15 ; 757,1429.5 580,1429.5 551,1400.5 321,1400.5 301,1380.5 ; 761.16,1271.66 640.16,1271.66 578,1209.5 399,1209.5 ; 893.34,1414.99 904.49,1414.99 913.55,1424.05 R134.2@913.55,1440.6 ; 301,1307.5 345.46,1307.5 399,1253.96 399,1209.5 ; 301,1307.5 301,1380.5 ; 362.18,1066.32 399,1103.14 399,1209.5
  BOTTOM w35: 148.85,839.85 v1(177,868) 187,858 324.01,858
3V3_MON_XDS_1: R158.2 R159.2 U9.8 | length 106
  BOTTOM w12: R159.2@24.43,608.61 U9.8@24.43,673.31
  BOTTOM w20: R159.2@24.43,608.61 65.54,608.61 R158.2@65.68,608.75
5V_IN: FB1.2 FB2.2 P5.1 R34.2 R78.2 R100.2 R103.2 R115.2 R117.2 R118.1 R149.2 R176.2 | length 2718.1
  TOP w20: R103.2@-11.33,500.07 v1(-11.33,531.5) ; v1(214,489.5) 216,489.5 216,490.16 R100.2@242.91,490.16 ; R117.2@308.61,411.05 317,419.44 v1(317,451.5) ; R78.2@1131.38,1088.29 1133.38,1090.29 v1(1159.19,1090.29) ; FB1.2@1495.18,483.01 FB2.2@1495.18,565.13 1668.47,565.13 1717.57,614.23 1717.57,769.57 1867,919 1879.11,919 1880.94,920.83 1887.33,920.83 v1(1916,949.5)
  TOP w30: v1(-11.33,531.5) -32,531.5 -56,555.5 -56,660 R176.2@-4,712
  L3 w20: v1(1159.19,1090.29) 1308.15,1090.29 1312.05,1094.19 1335.41,1094.19 1389.7,1148.47 1405.4,1148.47 1417.73,1160.8 1566.87,1160.8 1621.82,1105.85 1621.82,1065.13 1658.74,1028.2 1857.86,1028.2 1916,970.06 v1(1916,949.5)
  BOTTOM w20: v1(-11.33,531.5) 16.73,503.5 71.25,503.5 91.81,524.06 91.81,547.66 104.05,559.9 155.6,559.9 214,501.5 v1(214,489.5) ; v1(1916,949.5) 1916.14,949.64 R149.2@1916.14,982.46 R149.2@1916.14,983.25
  BOTTOM w30: v1(214,489.5) 252,451.5 v1(317,451.5) 351,417.5 351,383.5 451,283.5 v1(451,280.5)
  other v1: 562,219.5 510,221.5 474,241.5 1579,2109.5 1561,2141.5 1520,2156.5 1583,2174.5 1544,2184.5
5V_UNREG: C59.2 C60.2 C68.2 C72.2 C73.2 P5.2 R118.2 U8.9 U8.13 U8.18 U8.22 U8.26 | length 679.7
  TOP w25: v1(1730,431.5) 1716,431.5 1686.01,401.51 R118.2@1686.01,379.75 ; v1(1739,396.5) 1722.25,379.75 R118.2@1686.01,379.75 ; v1(1744,357.5) 1743,356.5 1709.26,356.5 R118.2@1686.01,379.75
  BOTTOM w10: 1465.59,1189.06 1503.26,1189.06 1511.63,1180.69 U8.9@1511.63,1141.13 ; 1498.57,951.17 1503.9,951.17 1511.63,958.9 U8.26@1511.63,1019.87 ; U8.22@1590.37,1019.87 1590.37,960.27 1595.3,955.34 1603.08,955.34 ; U8.13@1590.37,1141.13 1590.37,1183.19 1596.05,1188.86 1649.74,1188.86 ; U8.18@1625.81,1070.65 1665.16,1070.66 1669,1074.5 1692.82,1074.5 1700.32,1067 C68.2@1719.76,1067 1716.42,1070.34 v1(1716.42,1096.08)
  other v1: 1410,851 1689,851 1700,877 1410,879 1688,903 1401,907 1429,909 1656,911 1455,920 1631.87,1199.66 1661.71,1200.36 1439,1207 1470,1209 1680.9,1220.81 1652.89,1226.69 1453,1232
+3.3VD: C5.1 C20.2 C90.2 P2.2 P3.2 P4.2 R14.2 R15.2 R16.2 R37.1 R38.2 R41.2 R43.2 R68.2 R74.2 R90.2 R91.2 R125.2 R130.2 R133.2 R170.2 R171.2 R172.2 R173.2 R178.1 R189.2 U2.R13 U3.5 U13.14 | length 10127.1
  TOP w7.87: U13.14@1139.1,1199.34 v1(1166.57,1199.34)
  TOP w10: v1(974,858.48) 1002.52,887 1193.73,887 1246.5,834.23 R178.1@1246.5,825.86
  TOP w12: 2166.55,1694.7 2166.6,1694.65 U2.R13@2166.6,1657.03
  TOP w15: v1(1538.68,1896.5) 1577.39,1935.21 R43.2@1577.39,1950.4 ; v1(1630,2015) 1638,2023 R38.2@1638,2052.34
  TOP w19.68: R189.2@-14.4,286.41 v1(-14.4,316.79)
  TOP w20: R74.2@32.75,1221.14 v1(32.75,1259.5) 153.9,1380.65 153.9,1504.98 186.63,1537.71 186.63,1542.68 v1(216,1572.05) 216.79,1572.84 R68.2@246.04,1572.84 ; R91.2@149,757.57 v1(149,800) ; R90.2@200.46,756.69 v1(229,756.69) ; v1(614.45,2156.05) R16.2@638.2,2156.05 ; R14.2@638.26,2196.95 653.45,2196.95 v1(668,2211.5) ; v1(974,858.48) 987.19,845.29 987.19,835.45 987.39,835.25 U3.5@1042.01,835.25 ; R15.2@1062.49,2179.56 1063.86,2180.92 v1(1063.86,2204.17) ; v1(1166.57,1199.34) 1193.95,1199.34 C90.2@1196.58,1201.97 ; R125.2@1248.95,1234.12 1254.47,1239.64 v1(1254.47,1258.49) ; R37.1@2050.61,2037.7 v1(2080,2037.7) ; R41.2@2111.34,1884.48 v1(2139,1884.48) ; 2166.55,1694.7 C5.1@2166.55,1726.1 2167.47,1727.02 v1(2196,1727.02)
  L3 w20: v1(759.88,208.38) 760.94,207.32 v1(870.18,207.32) 1259.68,207.32 1305,162 v1(1305,110.5) ; v1(1371,1644.5) 1371,1702.77 1538.68,1870.45 v1(1538.68,1896.5) ; v1(1630,2015) 1656.19,1988.81 1716.01,1988.81 1797.54,2070.34 2047.36,2070.34 v1(2080,2037.7) 2139,1978.7 v1(2139,1884.48)
  L3 w25: v1(1166.57,1199.34) 1195.31,1199.34 v1(1254.47,1258.49)
  L3 w30: P4.2@818.44,768.75 909.56,768.75 979,699.31 979,672 v1(1053,598)
  L3 w35: v1(32.75,1259.5) 32.75,1158.15 82.4,1108.5 140.99,1108.5 220.51,1028.98 220.51,874.14 234.9,859.75 234.9,826 ; v1(149,800) 175,826 234.9,826 ; v1(229,756.69) 241.73,769.42 246.99,774.68 246.99,813.91 234.9,826 ; P4.2@818.44,768.75 818.44,847.23 872.04,900.83 931.65,900.83 v1(974,858.48)
  L3 w40: 241.73,769.42 P3.2@409,769.42 409.33,769.75 P2.2@612.44,769.75 629.74,787.05 746.82,787.05 765.12,768.75 P4.2@818.44,768.75
  L4 w20: v1(441,1923.5) 391,1973.5 391,2115.5 411,2135.5 593.9,2135.5 v1(614.45,2156.05) 668,2209.6 v1(668,2211.5) 631.64,2247.86 631.64,2278.23 698.3,2344.88 824.86,2344.88 965.58,2204.17 v1(1063.86,2204.17) 1065.85,2204.17 1102.43,2240.75 1531.64,2240.75 1558.05,2267.16 1637.7,2267.16 1714.91,2189.95 1714.91,2099.91 v1(1630,2015) 1630,1969.94 1556.55,1896.5 v1(1538.68,1896.5)
  L4 w25: v1(974,858.48) 1016.63,901.11 1016.63,958.14 1105.59,1047.11 1159,1047.11 1194.19,1082.3 1194.19,1141.98 1166.57,1169.6 v1(1166.57,1199.34)
  L4 w30: v1(2139,1884.48) 2143.47,1888.95 2192,1888.95 2213.38,1867.57 2213.38,1822.12 2245,1790.5 2245,1751.55 2220.47,1727.02 v1(2196,1727.02)
  L4 w40: v1(-14.4,316.79) -29.94,316.79 -53.75,340.6 -53.75,425.27 23.85,502.87 109.8,502.87 229,622.07 v1(229,756.69)
  BOTTOM w20: v1(216,1572.05) 187.14,1600.91 187.14,1638.64 269,1720.5 269,1792.51 399.99,1923.5 v1(441,1923.5) ; R173.2@759.88,180.84 v1(759.88,208.38) ; v1(870.18,207.32) R172.2@870.18,180.84 876.51,180.84 894.11,163.23 894.11,154 917.44,130.67 948.06,130.67 990.2,172.81 990.2,452.62 970.15,472.67 970.15,551.45 1016.7,598 v1(1053,598) ; v1(1305,110.5) 1317.5,123 1328,123 ; R171.2@1315.37,144.16 R171.2@1315.37,140.23 1315.37,135.63 1328,123 ; R170.2@1428.02,144.16 1428.02,143 1408.02,123 1328,123
  BOTTOM w25: R130.2@1358.81,1598.71 1358.81,1632.31 v1(1371,1644.5)
  BOTTOM w30: R133.2@1357.19,1529.05 1357.19,1597.09 R130.2@1358.81,1598.71
AR_1P3_RF1: C36.2 C37.2 C38.2 C45.1 C46.2 C47.1 L5.2 R131.2 U2.G5 U2.H5 U2.J5 U5.14 U5.15 | length 132.3
  TOP w10: U2.G5@2371.32,1452.31 U2.J5@2371.32,1503.49
  TOP w15: U2.G5@2371.32,1452.31 2387.56,1452.31 v1(2390.05,1454.8) ; U2.J5@2371.32,1503.49 2394.83,1503.49 v1(2396.62,1501.7)
  BOTTOM w20: C46.2@1748.19,1566.52 1748.43,1566.76 R131.2@1748.43,1601.78
  other v1: 1737.33,1629.38 1720.71,1644.84 1751.15,1647.68
AR_1P3_RF2: C28.2 C33.2 C34.2 C35.2 C57.1 C58.1 L8.2 R122.2 R137.1 U2.C2 U2.D2 U5.11 U5.12 | length 208.2
  TOP w10: U2.C2@2448.09,1349.95 U2.D2@2448.09,1375.54
  TOP w15: v1(2430.15,1371) 2434.69,1375.54 U2.D2@2448.09,1375.54
  TOP w20: 1678.94,1698.93 1682.8,1698.93 1711.9,1728.03 1711.9,1757.66 v1(1720.3,1766.07) v1(1743.7,1766.07) v1(1766.84,1766.07) ; v1(2400.5,1371.2) 2400.7,1371 v1(2430.15,1371)
AR_1V2: C3.1 C4.1 C6.1 C7.1 L9.2 U2.F13 U2.N11 U2.P14 U2.P15 U2.R6 U2.R14 | length 492.5
  TOP w10: 2071,1657.5 2097.06,1631.44 U2.P14@2141.01,1631.44 ; 2108,1706.54 2141.01,1673.53 U2.R14@2141.01,1657.03
  TOP w12: 2339.55,1706.05 2339,1705.5 2339,1683.5 2345.73,1676.77 U2.R6@2345.73,1657.03
  TOP w15: U2.F13@2166.6,1426.72 2183.67,1426.72 v1(2185.75,1428.8) ; U2.N11@2217.78,1605.85 2217.78,1601.72 2229.95,1589.55 v1(2229.95,1588.6)
  TOP w20: C6.1@2042.55,1718.5 C6.1@2042.55,1714.18 2071,1685.73 2071,1657.5 ; v1(2084,1732.5) 2090.22,1726.48 2105.35,1726.73 C4.1@2108,1727.74 2108,1706.54 ; 2339.55,1706.05 2339.55,1748.1 2362.25,1770.8 v1@2362.25,1800.5 ; v1(2362,1800.5) v1@2362.25,1800.5 ; v1@2364.31,1800.5 v1@2362.25,1800.5
  BOTTOM w20: v1(2006.84,1698.99) 2016.75,1708.9 v1(2016.75,1722.26)
  other v1: 1761.62,1528.79 1782.43,1549.59
AR_1V4_APLL: C13.1 U2.A10 | length 83.7
  TOP w20: 2238,1281.5 2238,1293.4 U2.A10@2243.37,1298.77
  TOP w25: C13.1@2234.45,1223.4 2228.91,1228.94 2228.91,1272.41 2238,1281.5
AR_1V4_SYNTH: C14.1 U2.A13 | length 98.7
  TOP w10: 2145.55,1277.72 U2.A13@2166.6,1298.77
  TOP w20: C14.1@2115.45,1221.3 2115.45,1247.62 2145.55,1277.72
AR_1V8: C12.1 C17.1 C18.1 C19.1 C39.1 C48.1 C51.1 C52.1 C53.1 C91.2 L7.2 R82.2 U2.B11 U2.B12 U2.D13 U2.F5 U2.K5 U2.K13 U4.1 U4.2 | length 833.1
  TOP w10: 2166.05,1260.37 2166.05,1273.9 2192.19,1300.04 U2.B12@2192.19,1324.36 ; C12.1@2182.55,1225.1 2189.95,1225.1 2204.8,1210.25 2204.8,1151.05 2184.27,1130.52 ; 2188.95,1271.46 2217.78,1300.29 U2.B11@2217.78,1324.36
  TOP w12: U2.F5@2371.32,1426.72 2377.83,1426.72
  TOP w15: U2.D13@2166.6,1375.54 2202.19,1375.54 v1(2206.65,1380) ; U2.K13@2166.6,1529.08 2182.87,1529.08 v1(2185.75,1526.2) ; C12.1@2182.55,1225.1 2188.95,1231.5 2188.95,1271.46 ; U2.K5@2371.32,1529.08 2380.18,1529.08 v1(2396.5,1545.4) ; 2377.83,1426.72 v1(2388.75,1415.8)
  TOP w20: v1(1965,995.04) C91.2@1965,1034.87 ; 2151.55,1114.8 2151.55,1245.87 2166.05,1260.37 ; 2172,1109.5 2172,1118.25 2184.27,1130.52
  BOTTOM w20: 2112.65,1392.98 C53.1@2112.65,1414 ; 2112.65,1435.02 C53.1@2112.65,1414 ; C53.1@2132.07,1414 C53.1@2116.97,1414 C53.1@2112.65,1414 ; v1(2388.75,1415.8) 2400.06,1427.11 2410.75,1427.11 2433.85,1450.21 C51.1@2435.27,1450.21 ; v1(2396.5,1545.4) 2411,1559.9 2411,1568.5 2437.8,1595.3 C39.1@2442.75,1595.3
  other v1: 2118,970.5 2128.79,1030.54 2168.81,1031.38 2115.68,1081.18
